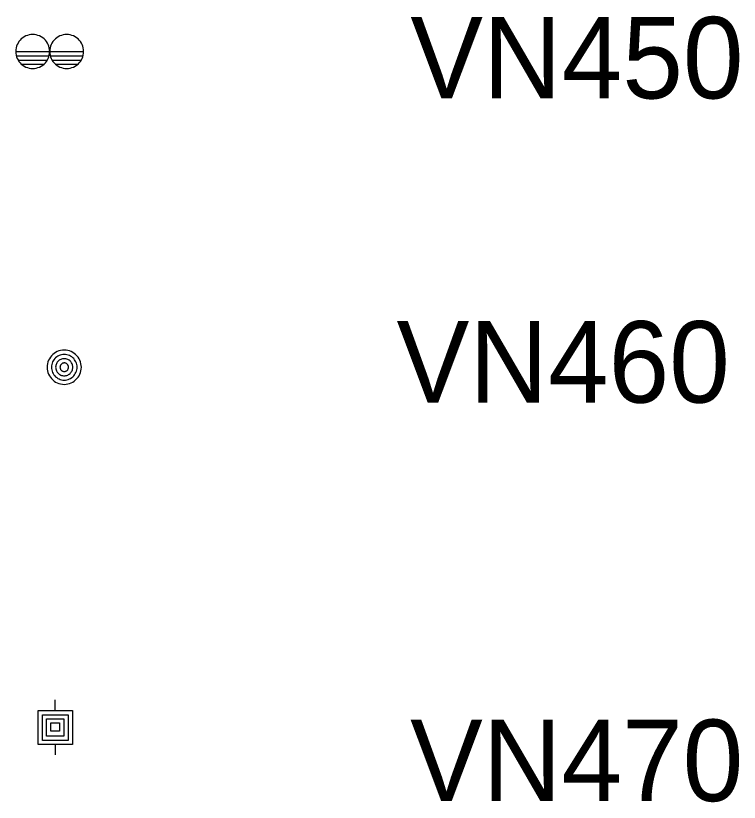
# Model space of a CAD drawing. Extents: x -592825 to -592404, y -1153473 to -1153230.
# Drawn here: x -592591.24 to -592577.92, y -1153396.93 to -1153382.45 of the extents above; entities that cross this region are included whole.
import ezdxf

# ---------------------------------------------------------------- set-up
doc = ezdxf.new("R2010")
doc.units = 0
doc.layers.add('Vrstva 45', color=7, linetype='Continuous')
doc.layers.add('Vrstva 63', color=7, linetype='Continuous')

msp = doc.modelspace()

# ---------------------------------------------------------------- linework, layer by layer
at = {"layer": 'Vrstva 45'}
for points in [[(-592590.615, -1153383.112), (-592590.617, -1153383.08), (-592590.622, -1153383.047), (-592590.631, -1153383.016), (-592590.642, -1153382.985), (-592590.657, -1153382.956), (-592590.675, -1153382.928), (-592590.695, -1153382.903), (-592590.719, -1153382.88), (-592590.744, -1153382.86), (-592590.771, -1153382.842), (-592590.801, -1153382.826), (-592590.831, -1153382.815), (-592590.863, -1153382.806), (-592590.895, -1153382.802), (-592590.927, -1153382.8), (-592590.961, -1153382.802), (-592590.993, -1153382.806), (-592591.024, -1153382.815), (-592591.055, -1153382.826), (-592591.084, -1153382.842), (-592591.111, -1153382.86), (-592591.137, -1153382.88), (-592591.159, -1153382.903), (-592591.181, -1153382.928), (-592591.198, -1153382.956), (-592591.213, -1153382.985), (-592591.225, -1153383.016), (-592591.233, -1153383.047), (-592591.239, -1153383.08), (-592591.24, -1153383.112), (-592591.239, -1153383.145), (-592591.233, -1153383.177), (-592591.225, -1153383.208), (-592591.213, -1153383.24), (-592591.198, -1153383.268), (-592591.181, -1153383.296), (-592591.159, -1153383.321), (-592591.137, -1153383.344), (-592591.111, -1153383.365), (-592591.083, -1153383.382), (-592591.055, -1153383.398), (-592591.024, -1153383.409), (-592590.993, -1153383.418), (-592590.961, -1153383.423), (-592590.927, -1153383.424), (-592590.895, -1153383.423), (-592590.863, -1153383.418), (-592590.831, -1153383.409), (-592590.801, -1153383.398), (-592590.771, -1153383.382), (-592590.744, -1153383.365), (-592590.719, -1153383.344), (-592590.695, -1153383.321), (-592590.675, -1153383.296), (-592590.657, -1153383.268), (-592590.642, -1153383.239), (-592590.631, -1153383.208), (-592590.622, -1153383.177), (-592590.617, -1153383.145), (-592590.615, -1153383.112)], [(-592589.99, -1153383.112), (-592589.992, -1153383.08), (-592589.997, -1153383.047), (-592590.005, -1153383.016), (-592590.017, -1153382.985), (-592590.032, -1153382.956), (-592590.05, -1153382.928), (-592590.071, -1153382.903), (-592590.093, -1153382.88), (-592590.119, -1153382.86), (-592590.147, -1153382.842), (-592590.175, -1153382.826), (-592590.206, -1153382.815), (-592590.237, -1153382.806), (-592590.27, -1153382.802), (-592590.303, -1153382.8), (-592590.335, -1153382.802), (-592590.367, -1153382.806), (-592590.399, -1153382.815), (-592590.43, -1153382.826), (-592590.459, -1153382.842), (-592590.486, -1153382.86), (-592590.511, -1153382.88), (-592590.535, -1153382.903), (-592590.555, -1153382.928), (-592590.573, -1153382.956), (-592590.588, -1153382.985), (-592590.599, -1153383.016), (-592590.609, -1153383.047), (-592590.613, -1153383.08), (-592590.615, -1153383.112), (-592590.613, -1153383.145), (-592590.609, -1153383.177), (-592590.599, -1153383.208), (-592590.588, -1153383.24), (-592590.573, -1153383.268), (-592590.555, -1153383.296), (-592590.535, -1153383.321), (-592590.511, -1153383.344), (-592590.486, -1153383.365), (-592590.459, -1153383.382), (-592590.429, -1153383.398), (-592590.399, -1153383.409), (-592590.367, -1153383.418), (-592590.335, -1153383.423), (-592590.303, -1153383.424), (-592590.27, -1153383.423), (-592590.237, -1153383.418), (-592590.206, -1153383.409), (-592590.175, -1153383.398), (-592590.146, -1153383.382), (-592590.119, -1153383.365), (-592590.093, -1153383.344), (-592590.071, -1153383.321), (-592590.05, -1153383.296), (-592590.032, -1153383.268), (-592590.017, -1153383.239), (-592590.005, -1153383.208), (-592589.997, -1153383.177), (-592589.992, -1153383.145), (-592589.99, -1153383.112)], [(-592591.24, -1153383.112), (-592589.99, -1153383.112)], [(-592591.23, -1153383.19), (-592590.625, -1153383.19)], [(-592591.195, -1153383.27), (-592590.659, -1153383.27)], [(-592590.605, -1153383.19), (-592590, -1153383.19)], [(-592590.571, -1153383.27), (-592590.034, -1153383.27)], [(-592591.131, -1153383.348), (-592590.723, -1153383.348)], [(-592590.507, -1153383.348), (-592590.099, -1153383.348)], [(-592590.032, -1153388.924), (-592590.034, -1153388.892), (-592590.039, -1153388.859), (-592590.047, -1153388.827), (-592590.059, -1153388.796), (-592590.075, -1153388.767), (-592590.093, -1153388.739), (-592590.113, -1153388.714), (-592590.137, -1153388.69), (-592590.162, -1153388.67), (-592590.189, -1153388.652), (-592590.219, -1153388.636), (-592590.25, -1153388.625), (-592590.281, -1153388.616), (-592590.314, -1153388.611), (-592590.347, -1153388.61), (-592590.38, -1153388.611), (-592590.413, -1153388.616), (-592590.445, -1153388.625), (-592590.475, -1153388.636), (-592590.505, -1153388.652), (-592590.532, -1153388.67), (-592590.558, -1153388.69), (-592590.581, -1153388.714), (-592590.602, -1153388.739), (-592590.62, -1153388.767), (-592590.635, -1153388.796), (-592590.647, -1153388.827), (-592590.655, -1153388.859), (-592590.661, -1153388.892), (-592590.662, -1153388.924), (-592590.661, -1153388.958), (-592590.655, -1153388.99), (-592590.647, -1153389.022), (-592590.635, -1153389.052), (-592590.62, -1153389.082), (-592590.602, -1153389.11), (-592590.581, -1153389.135), (-592590.558, -1153389.158), (-592590.532, -1153389.18), (-592590.505, -1153389.197), (-592590.475, -1153389.212), (-592590.445, -1153389.224), (-592590.413, -1153389.232), (-592590.38, -1153389.238), (-592590.347, -1153389.24), (-592590.314, -1153389.238), (-592590.281, -1153389.232), (-592590.25, -1153389.224), (-592590.219, -1153389.212), (-592590.189, -1153389.197), (-592590.162, -1153389.18), (-592590.137, -1153389.158), (-592590.113, -1153389.135), (-592590.093, -1153389.11), (-592590.075, -1153389.082), (-592590.059, -1153389.052), (-592590.047, -1153389.022), (-592590.039, -1153388.99), (-592590.034, -1153388.958), (-592590.032, -1153388.924)], [(-592590.111, -1153388.924), (-592590.112, -1153388.9), (-592590.116, -1153388.876), (-592590.123, -1153388.852), (-592590.131, -1153388.828), (-592590.143, -1153388.806), (-592590.156, -1153388.786), (-592590.171, -1153388.766), (-592590.189, -1153388.749), (-592590.209, -1153388.734), (-592590.229, -1153388.72), (-592590.251, -1153388.708), (-592590.274, -1153388.7), (-592590.298, -1153388.694), (-592590.323, -1153388.69), (-592590.347, -1153388.688), (-592590.371, -1153388.69), (-592590.396, -1153388.694), (-592590.42, -1153388.7), (-592590.443, -1153388.708), (-592590.465, -1153388.72), (-592590.486, -1153388.734), (-592590.505, -1153388.749), (-592590.523, -1153388.766), (-592590.538, -1153388.786), (-592590.551, -1153388.806), (-592590.563, -1153388.828), (-592590.572, -1153388.852), (-592590.578, -1153388.876), (-592590.582, -1153388.9), (-592590.583, -1153388.924), (-592590.582, -1153388.949), (-592590.578, -1153388.974), (-592590.572, -1153388.998), (-592590.563, -1153389.02), (-592590.551, -1153389.042), (-592590.538, -1153389.064), (-592590.523, -1153389.082), (-592590.505, -1153389.1), (-592590.486, -1153389.116), (-592590.465, -1153389.129), (-592590.443, -1153389.14), (-592590.42, -1153389.149), (-592590.396, -1153389.156), (-592590.371, -1153389.16), (-592590.347, -1153389.16), (-592590.323, -1153389.16), (-592590.298, -1153389.156), (-592590.274, -1153389.149), (-592590.251, -1153389.14), (-592590.229, -1153389.129), (-592590.209, -1153389.116), (-592590.189, -1153389.1), (-592590.171, -1153389.082), (-592590.156, -1153389.064), (-592590.143, -1153389.042), (-592590.131, -1153389.02), (-592590.123, -1153388.998), (-592590.116, -1153388.974), (-592590.112, -1153388.949), (-592590.111, -1153388.924)], [(-592590.189, -1153388.924), (-592590.191, -1153388.908), (-592590.193, -1153388.892), (-592590.197, -1153388.876), (-592590.203, -1153388.86), (-592590.211, -1153388.846), (-592590.219, -1153388.832), (-592590.23, -1153388.819), (-592590.241, -1153388.808), (-592590.255, -1153388.797), (-592590.269, -1153388.788), (-592590.283, -1153388.78), (-592590.299, -1153388.774), (-592590.315, -1153388.77), (-592590.331, -1153388.768), (-592590.347, -1153388.767), (-592590.363, -1153388.768), (-592590.38, -1153388.77), (-592590.396, -1153388.774), (-592590.411, -1153388.78), (-592590.426, -1153388.788), (-592590.439, -1153388.797), (-592590.453, -1153388.808), (-592590.464, -1153388.819), (-592590.475, -1153388.832), (-592590.483, -1153388.846), (-592590.491, -1153388.86), (-592590.497, -1153388.876), (-592590.501, -1153388.892), (-592590.503, -1153388.908), (-592590.505, -1153388.924), (-592590.503, -1153388.941), (-592590.501, -1153388.957), (-592590.497, -1153388.973), (-592590.491, -1153388.988), (-592590.483, -1153389.003), (-592590.475, -1153389.017), (-592590.464, -1153389.03), (-592590.453, -1153389.042), (-592590.439, -1153389.052), (-592590.426, -1153389.061), (-592590.411, -1153389.068), (-592590.396, -1153389.074), (-592590.38, -1153389.078), (-592590.363, -1153389.081), (-592590.347, -1153389.082), (-592590.331, -1153389.081), (-592590.315, -1153389.078), (-592590.299, -1153389.074), (-592590.283, -1153389.068), (-592590.269, -1153389.061), (-592590.255, -1153389.052), (-592590.241, -1153389.042), (-592590.23, -1153389.03), (-592590.219, -1153389.017), (-592590.211, -1153389.003), (-592590.203, -1153388.988), (-592590.197, -1153388.973), (-592590.193, -1153388.957), (-592590.191, -1153388.941), (-592590.189, -1153388.924)], [(-592590.269, -1153388.924), (-592590.269, -1153388.916), (-592590.27, -1153388.908), (-592590.272, -1153388.9), (-592590.275, -1153388.892), (-592590.279, -1153388.885), (-592590.283, -1153388.878), (-592590.289, -1153388.872), (-592590.295, -1153388.866), (-592590.301, -1153388.86), (-592590.308, -1153388.856), (-592590.315, -1153388.852), (-592590.323, -1153388.85), (-592590.331, -1153388.848), (-592590.339, -1153388.846), (-592590.347, -1153388.846), (-592590.355, -1153388.846), (-592590.363, -1153388.848), (-592590.371, -1153388.85), (-592590.379, -1153388.852), (-592590.387, -1153388.856), (-592590.393, -1153388.86), (-592590.4, -1153388.866), (-592590.405, -1153388.872), (-592590.411, -1153388.878), (-592590.415, -1153388.885), (-592590.419, -1153388.892), (-592590.422, -1153388.9), (-592590.424, -1153388.908), (-592590.425, -1153388.916), (-592590.426, -1153388.924), (-592590.425, -1153388.932), (-592590.424, -1153388.941), (-592590.422, -1153388.949), (-592590.419, -1153388.956), (-592590.415, -1153388.964), (-592590.411, -1153388.97), (-592590.405, -1153388.977), (-592590.4, -1153388.983), (-592590.393, -1153388.988), (-592590.387, -1153388.992), (-592590.379, -1153388.996), (-592590.371, -1153389), (-592590.363, -1153389.002), (-592590.355, -1153389.003), (-592590.347, -1153389.003), (-592590.339, -1153389.003), (-592590.331, -1153389.002), (-592590.323, -1153389), (-592590.315, -1153388.996), (-592590.308, -1153388.992), (-592590.301, -1153388.988), (-592590.295, -1153388.983), (-592590.289, -1153388.977), (-592590.283, -1153388.97), (-592590.279, -1153388.964), (-592590.275, -1153388.956), (-592590.272, -1153388.949), (-592590.27, -1153388.941), (-592590.269, -1153388.932), (-592590.269, -1153388.924)], [(-592590.513, -1153395.241), (-592590.513, -1153395.049)], [(-592590.828, -1153395.241), (-592590.198, -1153395.241)], [(-592590.828, -1153395.871), (-592590.828, -1153395.241)], [(-592590.749, -1153395.324), (-592590.277, -1153395.324)], [(-592590.749, -1153395.797), (-592590.749, -1153395.324)], [(-592590.277, -1153395.324), (-592590.277, -1153395.797)], [(-592590.198, -1153395.241), (-592590.198, -1153395.871)], [(-592590.671, -1153395.398), (-592590.355, -1153395.398)], [(-592590.671, -1153395.714), (-592590.671, -1153395.398)], [(-592590.591, -1153395.624), (-592590.591, -1153395.468)], [(-592590.591, -1153395.468), (-592590.435, -1153395.468)], [(-592590.435, -1153395.468), (-592590.435, -1153395.624)], [(-592590.355, -1153395.398), (-592590.355, -1153395.714)], [(-592590.355, -1153395.714), (-592590.671, -1153395.714)], [(-592590.435, -1153395.624), (-592590.591, -1153395.624)], [(-592590.198, -1153395.871), (-592590.828, -1153395.871)], [(-592590.277, -1153395.797), (-592590.749, -1153395.797)], [(-592590.513, -1153395.871), (-592590.513, -1153396.062)]]:
    msp.add_lwpolyline(points, dxfattribs=at)

# ---------------------------------------------------------------- texts
at = {"layer": 'Vrstva 63'}
for s, p in [('VN450', (-592583.977, -1153383.976)), ('VN460', (-592584.229, -1153389.576)), ('VN470', (-592583.981, -1153396.912))]:
    msp.add_text(s, height=1.5, dxfattribs=at).set_placement(p)

doc.saveas('drawing.dxf')
